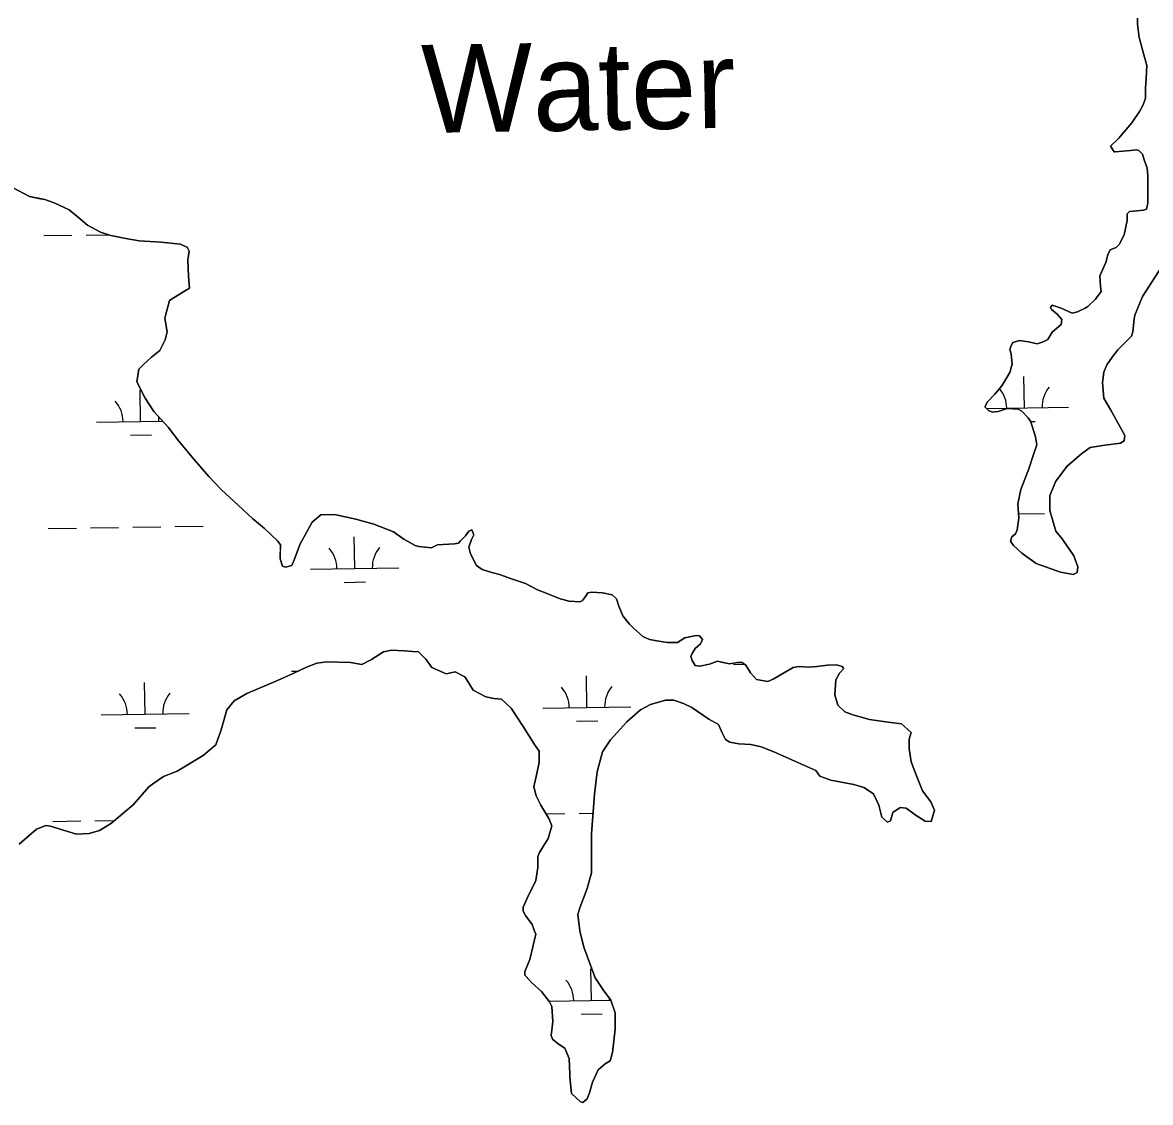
# Model space of a CAD drawing. Extents: x 3812694 to 3850888, y 319753 to 345638.
# Drawn here: x 3824379 to 3825660, y 334425 to 335652 of the extents above; entities that cross this region are included whole.
import ezdxf

# ---------------------------------------------------------------- set-up
doc = ezdxf.new("R2010")
doc.units = 0
for name, color, linetype in [('V-RIVR-IDEN', 7, 'Continuous'), ('V-TOPO-SHOR', 7, 'Continuous'), ('V-WETL-SWMP', 7, 'Continuous')]:
    doc.layers.add(name, color=color, linetype=linetype)

msp = doc.modelspace()

# ---------------------------------------------------------------- linework, layer by layer
at = {"layer": 'V-TOPO-SHOR'}
for points in [[(3825513, 335121.5), (3825521.9, 335144.7), (3825526.8, 335159.8), (3825530.9, 335172.1), (3825529.6, 335181), (3825524.2, 335198.1), (3825521.4, 335202.9), (3825513.9, 335210.4), (3825509.8, 335212.5), (3825497.5, 335213.2), (3825487.2, 335209.8), (3825480.4, 335209.2), (3825476.3, 335211.2), (3825472.2, 335215.4), (3825475, 335220.8), (3825483.2, 335229.7), (3825491.4, 335239.2), (3825500.4, 335254.3), (3825503.2, 335263.8), (3825501.8, 335275.5), (3825500.5, 335280.3), (3825501.8, 335285.1), (3825503.9, 335288.5), (3825511.4, 335290.5), (3825521.7, 335289.1), (3825531.3, 335287), (3825538.1, 335289.1), (3825543.6, 335291.8), (3825548.4, 335300), (3825558.7, 335308.8), (3825559.4, 335314.3), (3825554, 335320.5), (3825547.8, 335326), (3825546.5, 335328), (3825548.5, 335330.8), (3825558.8, 335327.3), (3825571.1, 335321.8), (3825577.2, 335323.1), (3825586.1, 335327.2), (3825588.9, 335329.3), (3825597.8, 335337.4), (3825604, 335346.3), (3825603.3, 335352.5), (3825602.7, 335364.1), (3825604.1, 335367.5), (3825609.6, 335379.2), (3825611.6, 335388), (3825614.4, 335393.5), (3825621.2, 335396.2), (3825624.7, 335399.6), (3825630.2, 335410.6), (3825633.7, 335427), (3825633.7, 335434.5), (3825636.4, 335437.2), (3825644.6, 335437.9), (3825652.2, 335438.5), (3825655.6, 335439.9), (3825657, 335446.7), (3825657, 335460.4), (3825657.1, 335478.2), (3825656.4, 335486.4), (3825653, 335496), (3825651, 335502.2), (3825646.9, 335506.3), (3825644.2, 335507), (3825637.3, 335506.3), (3825620.2, 335505), (3825618.8, 335505), (3825614.8, 335511.2), (3825623.7, 335520.1), (3825638.8, 335537.8), (3825647.7, 335550.8), (3825651.9, 335558.3), (3825654.6, 335565.8), (3825654.6, 335577.4), (3825655.4, 335588.4), (3825656.1, 335602.8), (3825653.4, 335612.3), (3825647.3, 335634.9), (3825645.3, 335650), (3825645.3, 335656.8)], [(3824361.1, 335467.8), (3824387.1, 335454.1), (3824397.3, 335452), (3824404.2, 335450.6), (3824415.1, 335447.1), (3824432.2, 335438.9), (3824443.1, 335430), (3824452.7, 335421.7), (3824467.7, 335413.5), (3824479.3, 335410), (3824496.4, 335406.5), (3824511.4, 335403.7), (3824536.1, 335402.3), (3824558.6, 335400.2), (3824565.5, 335396.7), (3824566.2, 335396.7), (3824568.2, 335391.9), (3824566.8, 335382.4), (3824567.4, 335363.2), (3824568.8, 335350.2), (3824561.2, 335345.4), (3824550.2, 335338.6), (3824546.1, 335335.9), (3824540.6, 335316.1), (3824543.3, 335300.3), (3824541.2, 335291.4), (3824535, 335279.1), (3824525.4, 335271.6), (3824516.5, 335263.5), (3824511, 335258), (3824508.9, 335243.6), (3824518.4, 335225.1), (3824528, 335210.1), (3824544.3, 335192.2), (3824556.6, 335176.4), (3824573.6, 335155.9), (3824590.7, 335136), (3824605, 335120.9), (3824624.1, 335103.7), (3824640.5, 335087.9), (3824653.4, 335077.6), (3824668.5, 335063.2), (3824671.9, 335058.4), (3824671.8, 335048.1), (3824671.8, 335042.7), (3824674.5, 335034.4), (3824677.9, 335033.1), (3824684.8, 335035.1), (3824688.2, 335043.3), (3824694.4, 335059.7), (3824700, 335069.9), (3824708.2, 335084.3), (3824717.8, 335092.5), (3824733.5, 335093.1), (3824757.5, 335087.6), (3824778, 335082), (3824800.5, 335073.1), (3824812.1, 335064.8), (3824825.1, 335057.9), (3824829.2, 335056.5), (3824843.6, 335055.1), (3824850.4, 335058.5), (3824869.6, 335059.8), (3824874.4, 335060.5), (3824876.5, 335063.2), (3824882, 335068.7), (3824886.1, 335074.2), (3824889.5, 335075.5), (3824891.5, 335070)], [(3825673.2, 335374.8), (3825651.2, 335340.7), (3825642.2, 335319.5), (3825641.5, 335315.4), (3825640.1, 335300.4), (3825638.7, 335295.6), (3825631.2, 335288.1), (3825622.9, 335279.9), (3825616.8, 335271.7), (3825610.6, 335262.8), (3825607.1, 335254.6), (3825605.7, 335243), (3825607, 335225.2), (3825615.2, 335211.5), (3825630.9, 335182.7), (3825630.1, 335176.6), (3825626, 335173.8), (3825608.2, 335171.8), (3825591.8, 335169.1), (3825582.2, 335162.3), (3825565.7, 335148), (3825552.7, 335131), (3825545.8, 335114.5), (3825545.7, 335097.4), (3825552.5, 335074.2), (3825560, 335065.2), (3825573, 335046), (3825577.7, 335033.7), (3825577, 335026.9), (3825572.9, 335024.8), (3825557.8, 335027.6), (3825530.5, 335037.3), (3825514.1, 335049), (3825504.6, 335057.9), (3825501.2, 335062.7), (3825502.5, 335067.5), (3825506.7, 335070.9), (3825508.7, 335075.7), (3825510.8, 335088.7), (3825509.5, 335105.1), (3825513, 335121.5)], [(3824891.5, 335070), (3824888.8, 335064.6), (3824886, 335055.7), (3824888, 335048.2), (3824894.8, 335035.1), (3824901, 335030.3), (3824911.9, 335026.9), (3824920.8, 335024.8), (3824934.5, 335020), (3824950.2, 335014.4), (3824963.9, 335007.5), (3824975.5, 335002.7), (3824989.8, 334997.2), (3825000.1, 334994.4), (3825012.4, 334993.7), (3825015.1, 334995.1), (3825018.6, 334999.9), (3825021.3, 335004), (3825025.4, 335004.6), (3825037.8, 335003.9), (3825048.7, 335001.8), (3825053.5, 334997), (3825056.2, 334988.8), (3825060.9, 334977.8), (3825068.4, 334968.2), (3825072.5, 334964.1), (3825083.4, 334954.5), (3825091, 334951), (3825101.9, 334949), (3825111.5, 334947.6), (3825123.1, 334947.5), (3825131.3, 334953), (3825144.3, 334955.7), (3825147.8, 334955), (3825151.2, 334950.9), (3825149.1, 334946.1), (3825142.9, 334940.6), (3825139.5, 334935.2), (3825138.1, 334931.7), (3825139.5, 334927), (3825142.9, 334921.5), (3825148.3, 334920.8), (3825159.3, 334922.8), (3825168.2, 334926.2), (3825171.6, 334925.5), (3825181.9, 334923.4), (3825191.5, 334924.7), (3825196.3, 334924.7), (3825200.4, 334922), (3825205.8, 334913.1), (3825212.6, 334905.5), (3825216.7, 334904.8), (3825225.6, 334903.4), (3825231.8, 334906.1), (3825242.7, 334912.3), (3825254.4, 334919.1), (3825260.6, 334920.4), (3825272.2, 334919.7), (3825281.1, 334920.4), (3825293.4, 334921.7), (3825303.7, 334922.3), (3825309.8, 334920.3), (3825311.9, 334918.2), (3825307.1, 334912.8), (3825302.9, 334905.2), (3825301.5, 334888.1), (3825304.9, 334876.5), (3825313.1, 334868.9), (3825322, 334865.5), (3825341.1, 334860), (3825362.3, 334857.2), (3825377.4, 334855.1), (3825388.3, 334845.4), (3825386.2, 334837.9), (3825386.2, 334827), (3825388.2, 334811.9), (3825394.3, 334796.2), (3825401.1, 334779), (3825410.6, 334766.7), (3825414.7, 334757.1), (3825411.2, 334744.1), (3825404.4, 334744.8), (3825394.1, 334751), (3825382.5, 334759.3), (3825375.7, 334760), (3825367.5, 334754.5), (3825364.7, 334744.9), (3825361.3, 334743.6), (3825355.1, 334749.1), (3825351.8, 334762.8), (3825345.6, 334775.8), (3825334.7, 334782.7), (3825323.1, 334786.1), (3825297.1, 334791), (3825284.8, 334795.8), (3825280, 334802), (3825263, 334809.6), (3825232.2, 334823.3), (3825217.9, 334828.9), (3825206.2, 334831.6), (3825192.6, 334832.4)], [(3825192.6, 334832.4), (3825182.3, 334834.4), (3825177.5, 334837.2), (3825174.1, 334844.1), (3825169.4, 334854.3), (3825158.4, 334860.5), (3825139.3, 334873.6), (3825129.7, 334878.4), (3825118.8, 334881.9), (3825109.2, 334881.9), (3825092.1, 334877.2), (3825081.1, 334871), (3825065.4, 334857.4), (3825046.8, 334836.9), (3825037.9, 334823.3), (3825031.7, 334800.7), (3825028.8, 334775.4), (3825025.3, 334730.2), (3825025.2, 334709), (3825025.1, 334685.8), (3825020.3, 334668), (3825012, 334646.1), (3825009.9, 334638.6), (3825011.9, 334620.1), (3825016.7, 334601.6), (3825024.1, 334581.1), (3825029.6, 334566.7), (3825038.4, 334553), (3825047.3, 334541.3), (3825052, 334526.9), (3825052, 334508.5), (3825049.1, 334481.8), (3825046.4, 334472.2), (3825040.9, 334468.8), (3825032.7, 334462), (3825026.5, 334448.3), (3825023, 334436), (3825020.2, 334429.2), (3825015.4, 334425.1), (3825012.7, 334425.8), (3825002.5, 334435.4), (3825000.5, 334453.9), (3825000.5, 334457.3), (3824999.9, 334475.1), (3824995.1, 334486.8), (3824987.6, 334491.6), (3824980.8, 334497.1), (3824979.4, 334501.2), (3824981.5, 334516.9), (3824980.2, 334534), (3824977.5, 334539.5), (3824968.6, 334551.2), (3824957, 334561.5), (3824950.9, 334568.3), (3824949.5, 334569.7), (3824949.5, 334573.8), (3824955.1, 334587.5), (3824962, 334616.2), (3824960.6, 334619.6), (3824957.9, 334627.1), (3824950.4, 334637.4), (3824947.7, 334642.2), (3824947.7, 334647), (3824952.5, 334657.9), (3824962.2, 334677.1), (3824964.3, 334692.1), (3824964.3, 334704.4), (3824966.4, 334709.2), (3824970.5, 334716), (3824976, 334724.9), (3824980.1, 334739.3), (3824976.8, 334747.5), (3824967.9, 334762.6), (3824962.5, 334773.5), (3824959.8, 334783.8), (3824963.2, 334798.9), (3824966, 334811.2), (3824966, 334824.2), (3824960.6, 334831.7), (3824947.7, 334852.3), (3824934, 334872.8), (3824923.1, 334883.1), (3824914.2, 334883.9), (3824905.3, 334885.9), (3824891, 334893.5), (3824883.5, 334905.2), (3824881.5, 334908.6), (3824870.5, 334914.1), (3824860.3, 334912.1), (3824843.9, 334919), (3824837, 334928.6), (3824828.9, 334936.8), (3824822, 334937.5), (3824812.4, 334938.2), (3824798.1, 334939), (3824789.2, 334936.9), (3824775.5, 334928.1), (3824764.5, 334922.6), (3824751.5, 334924.7), (3824724.8, 334925.5), (3824713.2, 334924.2)], [(3824713.2, 334924.2), (3824701.5, 334919.4), (3824687.1, 334912.6), (3824668.6, 334904.5), (3824633.7, 334889.5), (3824619.3, 334881.3), (3824611.1, 334871.1), (3824604.8, 334848.5), (3824598.6, 334831.5), (3824584.2, 334819.2), (3824554.7, 334801.5), (3824539, 334795.4), (3824528, 334787.9), (3824522.5, 334783.8), (3824504.7, 334763.3), (3824490.3, 334751.1), (3824480, 334742.2), (3824466.3, 334734), (3824454.6, 334730.6), (3824440.3, 334730), (3824426.6, 334734.1), (3824410.9, 334739), (3824405.4, 334739.7), (3824395.1, 334735.6), (3824375.2, 334718.6)]]:
    msp.add_lwpolyline(points, dxfattribs=at)
at = {"layer": 'V-WETL-SWMP'}
for p, q in [((3824403.2, 335409.7), (3824435.2, 335410.2)), ((3824451.2, 335410.4), (3824476.7, 335410.8)), ((3825516.9, 335213.9), (3825516.4, 335249.9)), ((3824513.2, 335198.7), (3824512.7, 335234.7)), ((3825474.3, 335213.3), (3825566.9, 335214.7)), ((3824463.2, 335198), (3824538, 335199.1)), ((3825523.9, 335198.6), (3825529.2, 335198.6)), ((3824501.5, 335183.1), (3824525.5, 335183.5)), ((3825510.4, 335093.7), (3825539.9, 335094.2)), ((3824408.2, 335077), (3824440.2, 335077.5)), ((3824456.2, 335077.8), (3824488.2, 335078.3)), ((3824504.2, 335078.5), (3824536.2, 335079)), ((3824552.2, 335079.2), (3824584.2, 335079.7)), ((3824756.3, 335031.6), (3824755.7, 335067.6)), ((3824706.3, 335030.8), (3824806.3, 335032.3)), ((3824744.5, 335015.9), (3824768.5, 335016.3)), ((3824684.6, 334915), (3824692.5, 334915.1)), ((3825186.5, 334922.6), (3825199.1, 334922.8)), ((3824518.3, 334866.1), (3824517.7, 334902.1)), ((3825020.1, 334873.7), (3825019.6, 334909.7)), ((3824468.3, 334865.3), (3824568.3, 334866.8)), ((3824970.1, 334872.9), (3825070.1, 334874.4)), ((3824506.5, 334850.5), (3824530.5, 334850.8)), ((3825008.4, 334858.1), (3825032.4, 334858.4)), ((3824973.6, 334752.9), (3824995.1, 334753.2)), ((3825011.1, 334753.4), (3825027.1, 334753.7)), ((3824413.3, 334744.4), (3824445.3, 334744.9)), ((3824461.3, 334745.1), (3824483.8, 334745.5)), ((3825025.2, 334541), (3825024.6, 334577)), ((3824976.9, 334540.3), (3825047.3, 334541.4)), ((3825013.4, 334525.4), (3825037.4, 334525.8))]:
    msp.add_line(p, q, dxfattribs=at)
for points in [[(3825645.3, 335656.8), (3825645.3, 335650), (3825647.3, 335634.9), (3825653.4, 335612.3), (3825656.1, 335602.8), (3825655.4, 335588.4), (3825654.6, 335577.4), (3825654.6, 335565.8), (3825651.9, 335558.3), (3825647.7, 335550.8), (3825638.8, 335537.8), (3825623.7, 335520.1), (3825614.8, 335511.2), (3825618.8, 335505), (3825620.2, 335505), (3825637.3, 335506.3), (3825644.2, 335507), (3825646.9, 335506.3), (3825651, 335502.2), (3825653, 335496), (3825656.4, 335486.4), (3825657.1, 335478.2), (3825657, 335446.7), (3825655.6, 335439.9), (3825652.2, 335438.5), (3825644.6, 335437.9), (3825636.4, 335437.2), (3825633.7, 335434.5), (3825633.7, 335427), (3825630.2, 335410.6), (3825624.7, 335399.6), (3825621.2, 335396.2), (3825614.4, 335393.5), (3825611.6, 335388), (3825609.6, 335379.2), (3825604.1, 335367.5), (3825602.7, 335364.1), (3825603.3, 335352.5), (3825604, 335346.3), (3825597.8, 335337.4), (3825588.9, 335329.3), (3825586.1, 335327.2), (3825577.2, 335323.1), (3825571.1, 335321.8), (3825558.8, 335327.3), (3825548.5, 335330.8), (3825546.5, 335328), (3825547.8, 335326), (3825554, 335320.5), (3825559.4, 335314.3), (3825558.7, 335308.8), (3825548.4, 335300), (3825543.6, 335291.8), (3825538.1, 335289.1), (3825531.3, 335287), (3825521.7, 335289.1), (3825511.4, 335290.5), (3825503.9, 335288.5), (3825501.8, 335285.1), (3825500.5, 335280.3), (3825501.8, 335275.5), (3825503.2, 335263.8), (3825500.4, 335254.3), (3825491.4, 335239.2), (3825483.2, 335229.7), (3825475, 335220.8), (3825472.2, 335215.4), (3825476.3, 335211.2), (3825480.4, 335209.2), (3825487.2, 335209.8), (3825497.5, 335213.2), (3825509.8, 335212.5), (3825513.9, 335210.4), (3825521.4, 335202.9), (3825524.2, 335198.1), (3825529.6, 335181), (3825530.9, 335172.1), (3825526.8, 335159.8)], [(3824825.1, 335057.9), (3824812.1, 335064.8), (3824800.5, 335073.1), (3824778, 335082), (3824757.5, 335087.6), (3824733.5, 335093.1), (3824717.8, 335092.5), (3824708.2, 335084.3), (3824700, 335069.9), (3824694.4, 335059.7), (3824688.2, 335043.3), (3824684.8, 335035.1), (3824677.9, 335033.1), (3824674.5, 335034.4), (3824671.8, 335042.7), (3824671.9, 335058.4), (3824668.5, 335063.2), (3824653.4, 335077.6), (3824640.5, 335087.9), (3824624.1, 335103.7), (3824605, 335120.9), (3824590.7, 335136), (3824573.6, 335155.9), (3824556.6, 335176.4), (3824544.3, 335192.2), (3824528, 335210.1), (3824518.4, 335225.1), (3824508.9, 335243.6), (3824511, 335258), (3824516.5, 335263.5), (3824525.4, 335271.6), (3824535, 335279.1), (3824541.2, 335291.4), (3824543.3, 335300.3), (3824540.6, 335316.1), (3824546.1, 335335.9), (3824550.2, 335338.6), (3824561.2, 335345.4), (3824568.8, 335350.2), (3824567.4, 335363.2), (3824566.8, 335382.4), (3824568.2, 335391.9), (3824566.2, 335396.7), (3824565.5, 335396.7), (3824558.6, 335400.2), (3824536.1, 335402.3), (3824511.4, 335403.7), (3824496.4, 335406.5), (3824479.3, 335410), (3824467.7, 335413.5), (3824452.7, 335421.7), (3824443.1, 335430), (3824432.2, 335438.9), (3824415.1, 335447.1), (3824404.2, 335450.6), (3824387.1, 335454.1), (3824361.1, 335467.8)], [(3825526.8, 335159.8), (3825521.9, 335144.7), (3825513, 335121.5), (3825509.5, 335105.1), (3825510.8, 335088.7), (3825508.7, 335075.7), (3825506.7, 335070.9), (3825502.5, 335067.5), (3825501.2, 335062.7), (3825504.6, 335057.9), (3825514.1, 335049), (3825530.5, 335037.3), (3825557.8, 335027.6), (3825572.9, 335024.8), (3825577, 335026.9), (3825577.7, 335033.7), (3825573, 335046), (3825560, 335065.2), (3825552.5, 335074.2), (3825545.7, 335097.4), (3825545.8, 335114.5), (3825552.7, 335131), (3825565.7, 335148), (3825582.2, 335162.3), (3825591.8, 335169.1), (3825608.2, 335171.8), (3825626, 335173.8), (3825630.1, 335176.6), (3825630.9, 335182.7), (3825615.2, 335211.5), (3825607, 335225.2), (3825605.7, 335243), (3825607.1, 335254.6), (3825610.6, 335262.8), (3825616.8, 335271.7), (3825622.9, 335279.9), (3825638.7, 335295.6), (3825640.1, 335300.4), (3825641.5, 335315.4), (3825642.2, 335319.5), (3825651.2, 335340.7), (3825673.2, 335374.8)], [(3825334.7, 334782.7), (3825345.6, 334775.8), (3825351.8, 334762.8), (3825355.1, 334749.1), (3825361.3, 334743.6), (3825364.7, 334744.9), (3825367.5, 334754.5), (3825375.7, 334760), (3825382.5, 334759.3), (3825394.1, 334751), (3825404.4, 334744.8), (3825411.2, 334744.1), (3825414.7, 334757.1), (3825410.6, 334766.7), (3825401.1, 334779), (3825394.3, 334796.2), (3825388.2, 334811.9), (3825386.2, 334827), (3825386.2, 334837.9), (3825388.3, 334845.4), (3825377.4, 334855.1), (3825362.3, 334857.2), (3825341.1, 334860), (3825322, 334865.5), (3825313.1, 334868.9), (3825304.9, 334876.5), (3825301.5, 334888.1), (3825302.9, 334905.2), (3825307.1, 334912.8), (3825311.9, 334918.2), (3825309.8, 334920.3), (3825303.7, 334922.3), (3825293.4, 334921.7), (3825281.1, 334920.4), (3825272.2, 334919.7), (3825260.6, 334920.4), (3825254.4, 334919.1), (3825242.7, 334912.3), (3825231.8, 334906.1), (3825225.6, 334903.4), (3825216.7, 334904.8), (3825212.6, 334905.5), (3825205.8, 334913.1), (3825200.4, 334922), (3825196.3, 334924.7), (3825191.5, 334924.7), (3825181.9, 334923.4), (3825168.2, 334926.2), (3825159.3, 334922.8), (3825148.3, 334920.8), (3825142.9, 334921.5), (3825139.5, 334927), (3825138.1, 334931.7), (3825139.5, 334935.2), (3825142.9, 334940.6), (3825149.1, 334946.1), (3825151.2, 334950.9), (3825147.8, 334955), (3825144.3, 334955.7), (3825131.3, 334953), (3825123.1, 334947.5), (3825111.5, 334947.6), (3825101.9, 334949), (3825091, 334951), (3825083.4, 334954.5), (3825072.5, 334964.1), (3825068.4, 334968.2), (3825060.9, 334977.8), (3825056.2, 334988.8), (3825053.5, 334997), (3825048.7, 335001.8), (3825037.8, 335003.9), (3825025.4, 335004.6), (3825021.3, 335004), (3825018.6, 334999.9), (3825015.1, 334995.1), (3825012.4, 334993.7), (3825000.1, 334994.4), (3824989.8, 334997.2), (3824975.5, 335002.7), (3824963.9, 335007.5), (3824950.2, 335014.4), (3824934.5, 335020), (3824920.8, 335024.8), (3824911.9, 335026.9), (3824901, 335030.3), (3824894.8, 335035.1), (3824888, 335048.2), (3824886, 335055.7), (3824888.8, 335064.6), (3824891.5, 335070), (3824889.5, 335075.5), (3824886.1, 335074.2), (3824882, 335068.7), (3824876.5, 335063.2), (3824874.4, 335060.5), (3824869.6, 335059.8), (3824850.4, 335058.5), (3824843.6, 335055.1), (3824829.2, 335056.5), (3824825.1, 335057.9)], [(3824375.2, 334718.6), (3824395.1, 334735.6), (3824405.4, 334739.7), (3824410.9, 334739), (3824426.6, 334734.1), (3824440.3, 334730), (3824454.6, 334730.6), (3824466.3, 334734), (3824480, 334742.2), (3824490.3, 334751.1), (3824504.7, 334763.3), (3824522.5, 334783.8), (3824528, 334787.9), (3824539, 334795.4), (3824554.7, 334801.5), (3824584.2, 334819.2), (3824598.6, 334831.5), (3824604.8, 334848.5), (3824611.1, 334871.1), (3824619.3, 334881.3), (3824633.7, 334889.5), (3824668.6, 334904.5), (3824687.1, 334912.6), (3824701.5, 334919.4), (3824713.2, 334924.2), (3824724.8, 334925.5), (3824751.5, 334924.7), (3824764.5, 334922.6), (3824775.5, 334928.1), (3824789.2, 334936.9), (3824798.1, 334939), (3824812.4, 334938.2), (3824822, 334937.5)], [(3824822, 334937.5), (3824828.9, 334936.8), (3824837, 334928.6), (3824843.9, 334919), (3824860.3, 334912.1), (3824870.5, 334914.1), (3824881.5, 334908.6), (3824883.5, 334905.2), (3824891, 334893.5), (3824905.3, 334885.9), (3824914.2, 334883.9), (3824923.1, 334883.1), (3824934, 334872.8), (3824947.7, 334852.3), (3824960.6, 334831.7), (3824966, 334824.2), (3824966, 334811.2), (3824963.2, 334798.9), (3824959.8, 334783.8), (3824962.5, 334773.5), (3824967.9, 334762.6), (3824976.8, 334747.5), (3824980.1, 334739.3), (3824976, 334724.9), (3824970.5, 334716), (3824966.4, 334709.2), (3824964.3, 334704.4), (3824964.3, 334692.1), (3824962.2, 334677.1), (3824952.5, 334657.9), (3824947.7, 334647), (3824947.7, 334642.2), (3824950.4, 334637.4), (3824957.9, 334627.1), (3824960.6, 334619.6), (3824962, 334616.2), (3824955.1, 334587.5), (3824949.5, 334573.8), (3824949.5, 334569.7), (3824950.9, 334568.3), (3824957, 334561.5), (3824968.6, 334551.2), (3824977.5, 334539.5), (3824980.2, 334534), (3824981.5, 334516.9), (3824979.4, 334501.2), (3824980.8, 334497.1), (3824987.6, 334491.6), (3824995.1, 334486.8), (3824999.9, 334475.1), (3825000.5, 334457.3), (3825000.5, 334453.9), (3825002.5, 334435.4), (3825012.7, 334425.8), (3825015.4, 334425.1), (3825020.2, 334429.2), (3825023, 334436), (3825026.5, 334448.3), (3825032.7, 334462), (3825040.9, 334468.8), (3825046.4, 334472.2), (3825049.1, 334481.8), (3825052, 334508.5), (3825052, 334526.9), (3825047.3, 334541.3), (3825038.4, 334553), (3825029.6, 334566.7), (3825024.1, 334581.1), (3825016.7, 334601.6), (3825011.9, 334620.1), (3825009.9, 334638.6), (3825012, 334646.1), (3825020.3, 334668), (3825025.1, 334685.8), (3825025.3, 334730.2), (3825028.8, 334775.4), (3825031.7, 334800.7), (3825037.9, 334823.3), (3825046.8, 334836.9), (3825065.4, 334857.4), (3825081.1, 334871), (3825092.1, 334877.2), (3825109.2, 334881.9), (3825118.8, 334881.9), (3825129.7, 334878.4), (3825139.3, 334873.6), (3825158.4, 334860.5), (3825169.4, 334854.3), (3825174.1, 334844.1), (3825177.5, 334837.2), (3825182.3, 334834.4), (3825192.5, 334832.4), (3825206.2, 334831.6), (3825217.9, 334828.9), (3825232.2, 334823.3), (3825263, 334809.6), (3825280, 334802), (3825284.8, 334795.8), (3825297.1, 334791), (3825323.1, 334786.1), (3825334.7, 334782.7)]]:
    msp.add_lwpolyline(points, dxfattribs=at)
for centre, start, end in [((3825461.7, 335213.5), 0.0949, 39.862), ((3825572.2, 335215.2), 140.0949, 181.6385), ((3824458, 335198.4), 0.0949, 41.6385), ((3824568.5, 335200), 173.4244, 181.6385), ((3824811.5, 335032.9), 140.0949, 181.6385), ((3824701, 335031.2), 0.0949, 41.6385), ((3824463, 334865.7), 0.0949, 41.6385), ((3824573.5, 334867.4), 140.0949, 181.6385), ((3824964.9, 334873.3), 0.0949, 41.6385), ((3825075.4, 334875), 140.0949, 181.6385), ((3824969.9, 334540.7), 0.0949, 41.6385), ((3825080.4, 334542.3), 177.1546, 181.6385)]:
    msp.add_arc(centre, 35.2, start, end, dxfattribs=at)

# ---------------------------------------------------------------- texts
at = {"layer": 'V-RIVR-IDEN'}
msp.add_text('Water', height=100, rotation=0.975, dxfattribs=at).set_placement((3824833, 335526.3))

doc.saveas('drawing.dxf')
